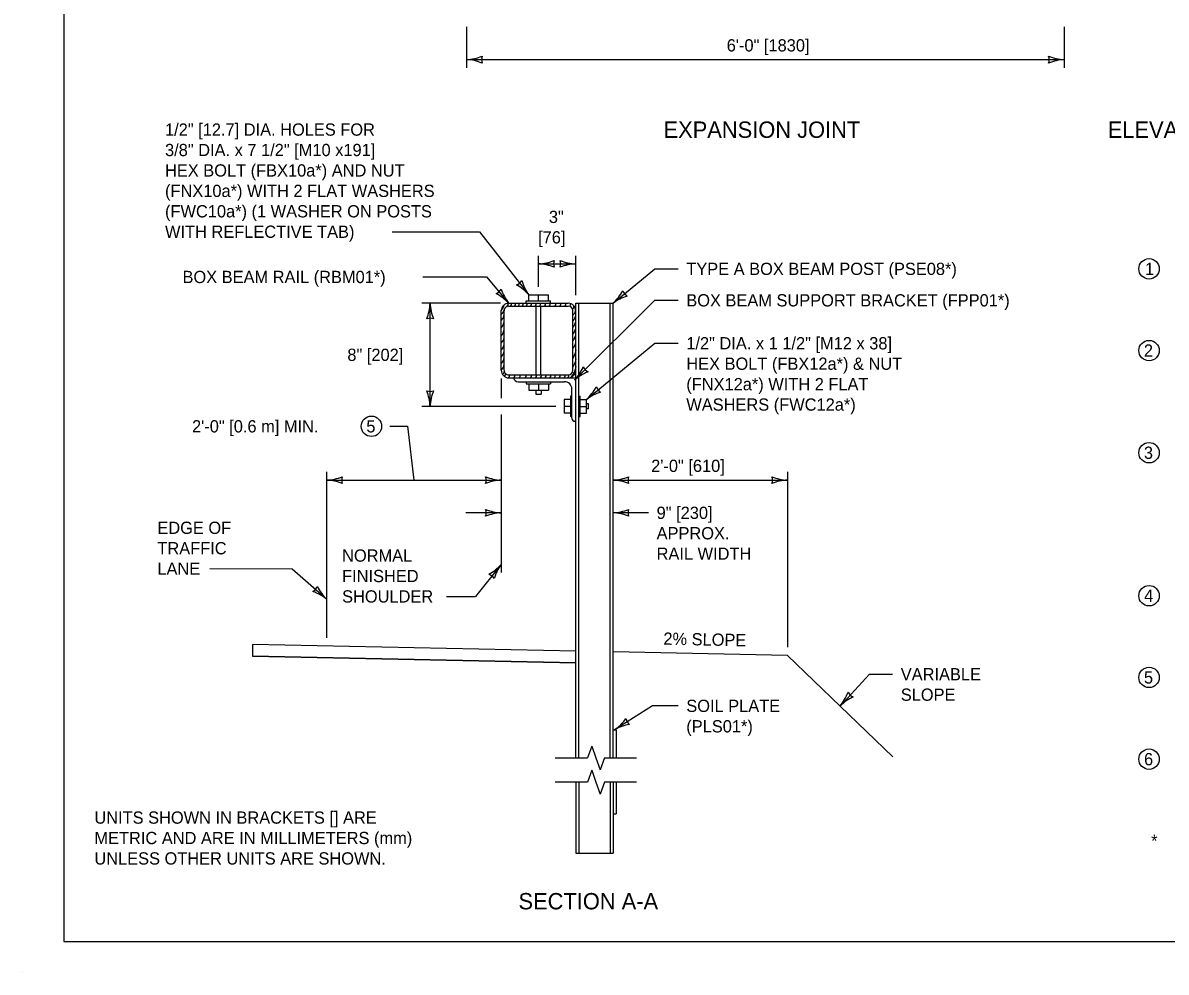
# Model space of a CAD drawing. Extents: x 49991.4 to 50021, y 49987.6 to 50011.4.
# Drawn here: x 50009.54 to 50015.13, y 49999.74 to 50004.38 of the extents above; entities that cross this region are included whole.
import ezdxf

# ---------------------------------------------------------------- set-up
doc = ezdxf.new("R2010")
doc.units = 0
for name, color, linetype in [('Level 1', 7, 'Continuous'), ('Level 2', 7, 'Continuous'), ('Level 3', 7, 'Continuous'), ('Level 6', 7, 'Continuous')]:
    doc.layers.add(name, color=color, linetype=linetype)

msp = doc.modelspace()

# ---------------------------------------------------------------- linework, layer by layer
at = {"layer": 'Level 1'}
for p, q in [((50012.0012, 50003.021), (50012.1206, 50003.021)), ((50012.0012, 50003.0097), (50012.0012, 50003.021)), ((50012.0135, 50003.021), (50012.0135, 50003.0505)), ((50012.0135, 50003.0505), (50012.1094, 50003.0505)), ((50012.0614, 50003.021), (50012.0614, 50003.0505)), ((50012.1094, 50003.021), (50012.1094, 50003.0505)), ((50012.1206, 50003.0097), (50012.1206, 50003.021)), ((50011.8786, 50002.6814), (50011.8786, 50002.9732)), ((50011.8932, 50002.6814), (50011.8932, 50002.9732)), ((50011.9151, 50003.0097), (50012.2069, 50003.0097)), ((50011.9151, 50002.9951), (50012.2069, 50002.9951)), ((50012.0495, 50002.6594), (50012.0495, 50002.9951)), ((50012.0724, 50002.6594), (50012.0724, 50002.9951)), ((50012.2289, 50002.6814), (50012.2289, 50002.9732)), ((50012.2434, 50000.7838), (50012.2434, 50003.0097)), ((50012.2434, 50003.0097), (50012.4259, 50003.0097)), ((50012.258, 50000.7838), (50012.258, 50003.0097)), ((50012.4113, 50000.7838), (50012.4113, 50003.0097)), ((50012.4259, 50000.7838), (50012.4259, 50003.0097)), ((50011.9151, 50002.6594), (50012.2069, 50002.6594)), ((50011.9151, 50002.6447), (50012.2434, 50002.6447)), ((50011.9612, 50002.6258), (50012.1878, 50002.6258)), ((50012.0014, 50002.6258), (50012.0014, 50002.6145)), ((50012.1207, 50002.6258), (50012.1207, 50002.6145)), ((50012.0014, 50002.6145), (50012.1207, 50002.6145)), ((50012.0137, 50002.6145), (50012.0137, 50002.5851)), ((50012.0137, 50002.5851), (50012.1094, 50002.5851)), ((50012.0611, 50002.6145), (50012.0611, 50002.5851)), ((50012.1094, 50002.6145), (50012.1094, 50002.5851)), ((50012.2246, 50002.4465), (50012.2246, 50002.5894)), ((50012.2171, 50002.5386), (50012.1867, 50002.5386)), ((50012.1867, 50002.5386), (50012.1867, 50002.4716)), ((50012.2171, 50002.5548), (50012.2171, 50002.4553)), ((50012.2246, 50002.5548), (50012.2171, 50002.5548)), ((50012.258, 50002.5548), (50012.2654, 50002.5548)), ((50012.2654, 50002.4553), (50012.2654, 50002.5548)), ((50012.2654, 50002.5386), (50012.2957, 50002.5386)), ((50012.2957, 50002.4716), (50012.2957, 50002.5386)), ((50012.3065, 50002.5169), (50012.2957, 50002.5169)), ((50012.3065, 50002.4935), (50012.3065, 50002.5169)), ((50012.2171, 50002.505), (50012.1867, 50002.505)), ((50012.2171, 50002.4716), (50012.1867, 50002.4716)), ((50012.2246, 50002.4553), (50012.2171, 50002.4553)), ((50012.258, 50002.4553), (50012.2654, 50002.4553)), ((50012.2654, 50002.505), (50012.2957, 50002.505)), ((50012.2654, 50002.4716), (50012.2957, 50002.4716)), ((50012.3065, 50002.4935), (50012.2957, 50002.4935)), ((50012.2434, 50002.4319), (50012.2391, 50002.4319)), ((50010.6621, 50001.3386), (50010.6621, 50001.2815)), ((50012.2434, 50001.3069), (50010.6621, 50001.3386)), ((50010.6621, 50001.3386), (50010.6621, 50001.2815)), ((50012.2434, 50001.2498), (50010.6621, 50001.2815)), ((50010.6621, 50001.2815), (50012.2434, 50001.2498)), ((50012.2434, 50001.2498), (50012.2434, 50001.3069)), ((50013.2799, 50001.2862), (50012.4259, 50001.3033)), ((50013.2799, 50001.2862), (50013.7947, 50000.7898)), ((50012.4259, 50000.9219), (50012.4411, 50000.9219)), ((50012.4411, 50000.9219), (50012.4411, 50000.7838)), ((50012.2434, 50000.6656), (50012.2434, 50000.318)), ((50012.2579, 50000.6656), (50012.2579, 50000.318)), ((50012.4113, 50000.6656), (50012.4113, 50000.318)), ((50012.4259, 50000.6656), (50012.4259, 50000.318)), ((50012.4411, 50000.6656), (50012.4411, 50000.5106)), ((50012.4259, 50000.5106), (50012.4411, 50000.5106)), ((50012.2434, 50000.318), (50012.4259, 50000.318)), ((50009.5374, 49999.7356), (50009.5374, 49999.7356))]:
    msp.add_line(p, q, dxfattribs=at)
msp.add_lwpolyline([(50020.9378, 50008.1646), (50009.7374, 50008.1646), (50009.7374, 49999.8856), (50020.9378, 49999.8856)], close=True, dxfattribs=at)
for points in [[(50011.8786, 50002.9747), (50011.886, 50002.9833), (50011.8892, 50002.9902), (50011.8932, 50003.0024)], [(50011.8786, 50002.9541), (50011.8854, 50002.9606), (50011.8896, 50002.9684), (50011.8945, 50002.9805)], [(50011.9058, 50002.993), (50011.9098, 50002.9964), (50011.9126, 50003.0018), (50011.9122, 50003.0096)], [(50011.9249, 50002.9951), (50011.9295, 50003.0023), (50011.9294, 50003.0097)], [(50011.9437, 50002.9951), (50011.9483, 50003.0023), (50011.9481, 50003.0097)], [(50011.9626, 50002.9951), (50011.9669, 50003.0018), (50011.9667, 50003.0097)], [(50011.9819, 50002.9951), (50011.9865, 50003.0022), (50011.986, 50003.0097)], [(50012.0015, 50002.9951), (50012.006, 50003.0022), (50012.0058, 50003.0097)], [(50012.0222, 50002.9951), (50012.0268, 50003.0022), (50012.0263, 50003.0097)], [(50012.0448, 50002.9951), (50012.0491, 50003.0018), (50012.0487, 50003.0097)], [(50012.0671, 50002.9951), (50012.0715, 50003.0022), (50012.0711, 50003.0097)], [(50012.0903, 50002.9951), (50012.095, 50003.0022), (50012.0946, 50003.0097)], [(50012.1141, 50002.9951), (50012.1185, 50003.0018), (50012.1182, 50003.0097)], [(50012.1419, 50002.9955), (50012.1464, 50003.0023), (50012.1459, 50003.0097)], [(50012.1657, 50002.9951), (50012.1703, 50003.0022), (50012.1699, 50003.0097)], [(50012.19, 50002.9951), (50012.1945, 50003.0022), (50012.1942, 50003.0097)], [(50012.2139, 50002.994), (50012.2184, 50003.0009), (50012.218, 50003.008)], [(50012.228, 50002.9793), (50012.2337, 50002.9879), (50012.2333, 50002.9984)], [(50012.2289, 50002.9508), (50012.2367, 50002.96), (50012.24, 50002.9668), (50012.2431, 50002.9775)], [(50011.8786, 50002.9259), (50011.8859, 50002.9346), (50011.8892, 50002.9415), (50011.8932, 50002.954)], [(50011.8786, 50002.8893), (50011.8854, 50002.8975), (50011.8887, 50002.9043), (50011.8932, 50002.9192)], [(50012.2289, 50002.9214), (50012.2361, 50002.9302), (50012.2395, 50002.937), (50012.2434, 50002.9498)], [(50012.2289, 50002.8914), (50012.2361, 50002.9), (50012.2395, 50002.9068), (50012.2434, 50002.9196)], [(50011.8786, 50002.8495), (50011.8854, 50002.8575), (50011.8887, 50002.8644), (50011.8932, 50002.879)], [(50012.2289, 50002.8584), (50012.2361, 50002.867), (50012.2395, 50002.874), (50012.2434, 50002.8867)], [(50012.2289, 50002.8258), (50012.2361, 50002.8345), (50012.2395, 50002.8414), (50012.2434, 50002.8542)], [(50011.8786, 50002.8139), (50011.8857, 50002.8225), (50011.8891, 50002.8294), (50011.8932, 50002.8429)], [(50011.8786, 50002.7801), (50011.8857, 50002.7886), (50011.8891, 50002.7956), (50011.8932, 50002.8088)], [(50012.2289, 50002.788), (50012.2361, 50002.7968), (50012.2395, 50002.8036), (50012.2434, 50002.8165)], [(50011.8786, 50002.7463), (50011.8857, 50002.755), (50011.8891, 50002.7618), (50011.8932, 50002.7751)], [(50011.8786, 50002.7134), (50011.8857, 50002.722), (50011.8891, 50002.7289), (50011.8932, 50002.7424)], [(50012.2434, 50002.781), (50012.2404, 50002.766), (50012.2364, 50002.7534), (50012.2289, 50002.7399)], [(50012.2434, 50002.7383), (50012.24, 50002.7218), (50012.2362, 50002.7094), (50012.2289, 50002.6965)], [(50011.8786, 50002.6812), (50011.8857, 50002.6897), (50011.8891, 50002.6966), (50011.8932, 50002.7099)], [(50011.8933, 50002.6789), (50011.8915, 50002.6701), (50011.8887, 50002.6647), (50011.8838, 50002.6625)], [(50012.2434, 50002.7002), (50012.24, 50002.686), (50012.2362, 50002.673), (50012.2295, 50002.6604), (50012.2188, 50002.6467)], [(50011.8945, 50002.6511), (50011.8995, 50002.659), (50011.899, 50002.6665)], [(50011.9147, 50002.6447), (50011.9198, 50002.6519), (50011.9194, 50002.6594)], [(50011.9402, 50002.6447), (50011.9446, 50002.6514), (50011.9443, 50002.6594)], [(50011.9674, 50002.6447), (50011.9718, 50002.6514), (50011.9715, 50002.6594)], [(50011.9959, 50002.6447), (50012.0007, 50002.6519), (50012.0004, 50002.6594)], [(50012.0213, 50002.6447), (50012.0262, 50002.6519), (50012.0259, 50002.6594)], [(50012.0462, 50002.6447), (50012.0509, 50002.6519), (50012.0507, 50002.6594)], [(50012.0702, 50002.6447), (50012.0753, 50002.6524), (50012.0749, 50002.6594)], [(50012.0933, 50002.6447), (50012.0985, 50002.6526), (50012.0982, 50002.6594)], [(50012.1173, 50002.6447), (50012.122, 50002.6519), (50012.1219, 50002.6594)], [(50012.1387, 50002.6447), (50012.1435, 50002.6519), (50012.143, 50002.6594)], [(50012.1628, 50002.6447), (50012.1675, 50002.6519), (50012.1673, 50002.6594)], [(50012.1865, 50002.6447), (50012.1911, 50002.6518), (50012.1907, 50002.6594)], [(50012.2049, 50002.6447), (50012.2095, 50002.6519), (50012.2093, 50002.6595)], [(50012.0483, 50002.5851), (50012.0483, 50002.5639)], [(50012.0737, 50002.5851), (50012.0737, 50002.5639)], [(50012.0483, 50002.5639), (50012.0737, 50002.5639)]]:
    msp.add_lwpolyline(points, dxfattribs=at)
for centre, radius, start, end in [((50011.9151, 50002.9732), 0.0365, 90, 180), ((50011.9151, 50002.9732), 0.0219, 90, 180.0772), ((50012.2069, 50002.9732), 0.0365, 0, 90), ((50012.2069, 50002.9731), 0.022, 0.1305, 90.1305), ((50011.9152, 50002.6813), 0.0366, 179.8435, 269.8435), ((50011.9152, 50002.6813), 0.022, 179.8695, 269.8695), ((50012.2069, 50002.6814), 0.022, 270, 0), ((50012.2068, 50002.6813), 0.0366, 270.1565, 0.1565), ((50011.9612, 50002.6477), 0.0219, 187.8518, 269.9472), ((50012.188, 50002.5892), 0.0366, 0.3131, 90.3131), ((50012.2392, 50002.4464), 0.0146, 179.8031, 269.8031)]:
    msp.add_arc(centre, radius, start, end, dxfattribs=at)
at = {"layer": 'Level 2'}
for centre in [(50015.0495, 50003.1781), (50015.0495, 50002.7781), (50011.2434, 50002.4074), (50015.0495, 50002.2781), (50015.0495, 50001.5781), (50015.0495, 50001.1781), (50015.0495, 50000.7781)]:
    msp.add_circle(centre, 0.05, dxfattribs=at)
at = {"layer": 'Level 3'}
for p, q in [((50012.4259, 50003.0097), (50012.6309, 50003.1781)), ((50012.6309, 50003.0241), (50012.2378, 50002.6327)), ((50012.6309, 50003.0241), (50012.7446, 50003.0241)), ((50011.5306, 50002.5051), (50011.5306, 50003.0097)), ((50012.2957, 50002.5386), (50012.6309, 50002.8139)), ((50011.8786, 50002.6414), (50011.8786, 50002.545)), ((50011.8787, 50002.4651), (50011.8786, 50001.6917)), ((50011.3333, 50002.4074), (50011.4201, 50002.4074)), ((50011.4201, 50002.4074), (50011.4516, 50002.1439)), ((50011.0246, 50001.3713), (50011.0246, 50002.1839)), ((50013.2799, 50002.1839), (50013.2799, 50001.3262)), ((50011.0246, 50002.1439), (50011.8786, 50002.1439)), ((50012.4259, 50002.1439), (50013.2799, 50002.1439)), ((50011.8786, 50001.9839), (50011.7052, 50001.9839)), ((50012.5993, 50001.984), (50012.4259, 50001.984)), ((50011.8786, 50001.7317), (50011.7522, 50001.5747)), ((50010.4526, 50001.7106), (50010.8547, 50001.7105)), ((50010.8547, 50001.7105), (50011.0246, 50001.5608)), ((50011.6102, 50001.5747), (50011.7522, 50001.5747)), ((50013.5372, 50001.0381), (50013.6806, 50001.1938))]:
    msp.add_line(p, q, dxfattribs=at)
for points in [[(50011.7092, 50004.3622), (50011.7091, 50004.1622)], [(50014.6342, 50004.3622), (50014.6342, 50004.1622)], [(50011.7091, 50004.2022), (50014.6342, 50004.2022)], [(50011.3447, 50003.3599), (50011.7728, 50003.3599)], [(50011.7728, 50003.3599), (50012.0135, 50003.0505)], [(50012.0614, 50003.0905), (50012.0615, 50003.2425)], [(50012.2434, 50003.0497), (50012.2434, 50003.2425)], [(50012.0615, 50003.2025), (50012.2434, 50003.2025)], [(50011.4947, 50003.1385), (50011.8068, 50003.1385), (50011.9151, 50003.0097)], [(50012.6309, 50003.1781), (50012.7446, 50003.1781)], [(50011.8751, 50003.0097), (50011.4906, 50003.0097)], [(50012.6309, 50002.8139), (50012.7446, 50002.8139)], [(50012.1467, 50002.505), (50011.4906, 50002.5051)], [(50013.6806, 50001.1938), (50013.7943, 50001.1938)], [(50012.7446, 50001.039), (50012.6198, 50001.039), (50012.4335, 50000.9219)]]:
    msp.add_lwpolyline(points, dxfattribs=at)
for centre, radius, start, end in [((50011.6976, 50004.4349), 0.233, 272.8273, 292.0772), ((50011.6999, 50003.9801), 0.2223, 67.456, 87.6395), ((50011.8373, 50004.2022), 0.0548, 162.1388, 197.8612), ((50014.6434, 50004.4243), 0.2223, 247.456, 267.6395), ((50014.506, 50004.2022), 0.0548, 342.1388, 17.8612), ((50014.6457, 50003.9695), 0.233, 92.8273, 112.0772), ((50012.05, 50003.4352), 0.233, 272.8273, 292.0772), ((50012.0523, 50002.9804), 0.2223, 67.456, 87.6395), ((50012.1897, 50003.2025), 0.0548, 162.1388, 197.8612), ((50012.2526, 50003.4246), 0.2223, 247.456, 267.6395), ((50012.1152, 50003.2025), 0.0548, 342.1388, 17.8612), ((50012.2549, 50002.9698), 0.233, 92.8273, 112.0772), ((50011.8326, 50003.1078), 0.0548, 292.1972, 327.9196), ((50012.091, 50003.1456), 0.2223, 197.5144, 217.6979), ((50011.9348, 50003.1517), 0.0548, 290.0175, 325.7398), ((50011.8369, 50002.8985), 0.233, 40.706, 59.9558), ((50012.1945, 50003.1797), 0.2223, 195.3347, 215.5182), ((50012.2693, 50003.1822), 0.233, 312.2292, 331.479), ((50012.525, 50003.0911), 0.0548, 201.5407, 237.263), ((50011.7444, 50002.8511), 0.233, 42.8857, 62.1356), ((50012.5598, 50002.8322), 0.2223, 106.8579, 127.0414), ((50011.3085, 50003.0189), 0.2223, 337.456, 357.6395), ((50011.7633, 50003.0212), 0.233, 182.8273, 202.0772), ((50011.5306, 50002.8815), 0.0548, 72.1388, 107.8612), ((50012.0655, 50002.7895), 0.233, 317.7032, 336.953), ((50012.3287, 50002.7232), 0.0548, 207.0147, 242.737), ((50012.388, 50002.4688), 0.2223, 112.3319, 132.5154), ((50011.5306, 50002.6333), 0.0548, 252.1388, 287.8612), ((50011.2979, 50002.4936), 0.233, 2.8273, 22.0772), ((50011.7527, 50002.4959), 0.2223, 157.456, 177.6395), ((50012.1391, 50002.7111), 0.233, 312.2236, 331.4734), ((50012.4296, 50002.3611), 0.2223, 106.8523, 127.0358), ((50012.3948, 50002.62), 0.0548, 201.5351, 237.2575), ((50011.0131, 50002.3766), 0.233, 272.8273, 292.0772), ((50011.0154, 50001.9218), 0.2223, 67.456, 87.6395), ((50011.1528, 50002.1439), 0.0548, 162.1388, 197.8612), ((50011.8878, 50002.366), 0.2223, 247.456, 267.6395), ((50011.7504, 50002.1439), 0.0548, 342.1388, 17.8612), ((50011.8901, 50001.9112), 0.233, 92.8273, 112.0772), ((50012.4144, 50002.3766), 0.233, 272.8273, 292.0772), ((50012.4167, 50001.9218), 0.2223, 67.456, 87.6395), ((50012.5541, 50002.1439), 0.0548, 162.1388, 197.8612), ((50013.2891, 50002.366), 0.2223, 247.456, 267.6395), ((50013.1517, 50002.1439), 0.0548, 342.1388, 17.8612), ((50013.2914, 50001.9112), 0.233, 92.8273, 112.0772), ((50011.8878, 50002.206), 0.2223, 247.456, 267.6395), ((50011.7504, 50001.9839), 0.0548, 342.1388, 17.8612), ((50011.8901, 50001.7512), 0.233, 92.8273, 112.0772), ((50012.4144, 50002.2167), 0.233, 272.8273, 292.0772), ((50012.4167, 50001.7618), 0.2223, 67.456, 87.6395), ((50012.5541, 50001.984), 0.0548, 162.1388, 197.8612), ((50011.7113, 50001.8781), 0.2223, 298.612, 318.7955), ((50012.0671, 50001.5947), 0.233, 143.9833, 163.2332), ((50011.7982, 50001.6318), 0.0548, 33.2948, 69.0172), ((50010.9284, 50001.6456), 0.0548, 300.7491, 336.4715), ((50011.1783, 50001.7214), 0.2223, 206.0663, 226.2498), ((50010.8794, 50001.3786), 0.233, 51.4376, 70.6874), ((50013.3582, 50001.1872), 0.233, 320.2005, 339.4504), ((50013.6945, 50000.8809), 0.2223, 114.8292, 135.0127), ((50013.6241, 50001.1324), 0.0548, 209.512, 245.2344), ((50012.2999, 50001.1128), 0.233, 304.979, 324.2288), ((50012.544, 50000.729), 0.2223, 99.6077, 119.7912), ((50012.5421, 50000.9901), 0.0548, 194.2905, 230.0128)]:
    msp.add_arc(centre, radius, start, end, dxfattribs=at)
at = {"layer": 'Level 6'}
for p, q in [((50012.3215, 50000.8423), (50012.3008, 50000.7838)), ((50012.3215, 50000.8423), (50012.3423, 50000.7838)), ((50012.1434, 50000.7838), (50012.3008, 50000.7838)), ((50012.3423, 50000.7838), (50012.363, 50000.7254)), ((50012.3837, 50000.7838), (50012.363, 50000.7254)), ((50012.3837, 50000.7838), (50012.5411, 50000.7838)), ((50012.3215, 50000.7241), (50012.3008, 50000.6656)), ((50012.3215, 50000.7241), (50012.3423, 50000.6656)), ((50012.3008, 50000.6656), (50012.1434, 50000.6656)), ((50012.3423, 50000.6656), (50012.363, 50000.6071)), ((50012.3837, 50000.6656), (50012.363, 50000.6071)), ((50012.5411, 50000.6656), (50012.3837, 50000.6656))]:
    msp.add_line(p, q, dxfattribs=at)

# ---------------------------------------------------------------- texts
at = {"layer": 'Level 2'}
for s, height, p in [('6\'-0" [1830]', 0.06, (50012.9825, 50004.2422)), ('1/2" [12.7] DIA. HOLES FOR  ', 0.06, (50010.2332, 50003.8299)), ('EXPANSION JOINT', 0.08, (50012.6732, 50003.8194)), ('ELEVATION', 0.08, (50014.8472, 50003.8194)), ('3/8" DIA. x 7 1/2" [M10 x191] ', 0.06, (50010.2332, 50003.7299)), ('HEX BOLT (FBX10a*) AND NUT', 0.06, (50010.2332, 50003.6299)), ('(FNX10a*) WITH 2 FLAT WASHERS', 0.06, (50010.2332, 50003.5299)), ('(FWC10a*) (1 WASHER ON POSTS', 0.06, (50010.2332, 50003.4299)), ('3"', 0.06, (50012.1121, 50003.4025)), ('WITH REFLECTIVE TAB)', 0.06, (50010.2332, 50003.3299)), ('[76]', 0.06, (50012.0592, 50003.3025)), ('TYPE A BOX BEAM POST (PSE08*)', 0.06, (50012.7846, 50003.1481)), ('1', 0.06, (50015.0297, 50003.1481)), ('BOX BEAM RAIL (RBM01*)', 0.06, (50010.3188, 50003.1085)), ('BOX BEAM SUPPORT BRACKET (FPP01*)', 0.06, (50012.7846, 50002.9941)), ('1/2" DIA. x 1 1/2" [M12 x 38]', 0.06, (50012.7846, 50002.7839)), ('8" [202]', 0.06, (50011.1256, 50002.7274)), ('2', 0.06, (50015.0243, 50002.7481)), ('HEX BOLT (FBX12a*) & NUT ', 0.06, (50012.7846, 50002.6839)), ('(FNX12a*) WITH 2 FLAT', 0.06, (50012.7846, 50002.5839)), ('WASHERS (FWC12a*)', 0.06, (50012.7846, 50002.4839)), ('2\'-0" [0.6 m] MIN.', 0.06, (50010.3654, 50002.3774)), ('5', 0.06, (50011.2184, 50002.3774)), ('3', 0.06, (50015.0243, 50002.2481)), ('2\'-0" [610]', 0.06, (50012.6126, 50002.1839)), ('9" [230]', 0.06, (50012.6393, 50001.954)), ('EDGE OF', 0.06, (50010.1958, 50001.8806)), ('APPROX.', 0.06, (50012.6393, 50001.854)), ('TRAFFIC', 0.06, (50010.1958, 50001.7806)), ('NORMAL', 0.06, (50011.0999, 50001.7447)), ('RAIL WIDTH', 0.06, (50012.6393, 50001.754)), ('LANE', 0.06, (50010.1958, 50001.6806)), ('FINISHED', 0.06, (50011.0999, 50001.6447)), ('SHOULDER', 0.06, (50011.0999, 50001.5447)), ('4', 0.06, (50015.0255, 50001.5481)), ('VARIABLE', 0.06, (50013.8343, 50001.1638)), ('5', 0.06, (50015.0246, 50001.1481)), ('SLOPE', 0.06, (50013.8343, 50001.0638)), ('SOIL PLATE', 0.06, (50012.7846, 50001.009)), ('(PLS01*)', 0.06, (50012.7846, 50000.909)), ('6', 0.06, (50015.025, 50000.7481)), ('UNITS SHOWN IN BRACKETS [] ARE', 0.06, (50009.8875, 50000.4622)), ('METRIC AND ARE IN MILLIMETERS (mm)', 0.06, (50009.8875, 50000.3622)), ('*', 0.06, (50015.0597, 50000.3481)), ('UNLESS OTHER UNITS ARE SHOWN.', 0.06, (50009.8875, 50000.2622)), ('SECTION A-A', 0.08, (50011.9631, 50000.0428))]:
    msp.add_text(s, height=height, dxfattribs=at).set_placement(p)
msp.add_text('2% SLOPE', height=0.06, rotation=358.8516, dxfattribs=at).set_placement((50012.6719, 50001.3384))

doc.saveas('drawing.dxf')
